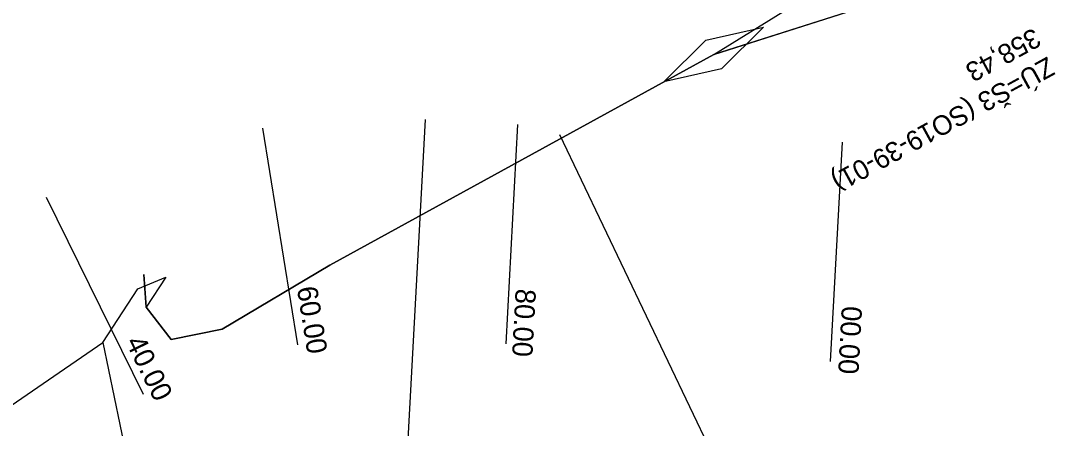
# Model space of a CAD drawing. Extents: x -783978 to -783565, y -1064821 to -1064596.
# Drawn here: x -783930.1 to -783865.7, y -1064776.5 to -1064751.5 of the extents above; entities that cross this region are included whole.
import ezdxf

# ---------------------------------------------------------------- set-up
doc = ezdxf.new("R2010")
doc.units = 0
for name, color, linetype in [('_PS_SO_číslo', 7, 'Continuous'), ('PS 01_02_501', 7, 'Continuous'), ('PS 01_02_502', 7, 'Continuous'), ('SO 01_31_01', 7, 'Continuous'), ('SO 01_50_01', 7, 'Continuous'), ('SO 01_86_02', 7, 'Continuous'), ('SO 01_86_03', 7, 'Continuous')]:
    doc.layers.add(name, color=color, linetype=linetype)

msp = doc.modelspace()

# ---------------------------------------------------------------- linework, layer by layer
at = {"layer": '_PS_SO_číslo'}
for p, q in [((-783896.924, -1064758.44), (-783883.182, -1064787.145)), ((-783925.027, -1064771.233), (-783915.428, -1064817.268))]:
    msp.add_line(p, q, dxfattribs=at)
at = {"layer": 'PS 01_02_501'}
for points in [[(-783952.311, -1064789.972), (-783925.027, -1064771.233), (-783922.857, -1064767.935), (-783921.132, -1064767.225), (-783922.344, -1064769.056), (-783920.816, -1064771.043), (-783917.67, -1064770.417), (-783911.05, -1064766.471), (-783887.429, -1064753.525), (-783871.436, -1064748.425), (-783783.828, -1064700.439), (-783789.362, -1064690.348), (-783735.226, -1064660.707), (-783727.19, -1064659.072), (-783724.297, -1064658.484), (-783715.521, -1064653.988), (-783697.391, -1064644.148), (-783676.268, -1064633.506), (-783655.138, -1064621.894)], [(-783890.501, -1064755.202), (-783887.908, -1064752.647), (-783884.357, -1064751.848), (-783886.95, -1064754.403), (-783890.501, -1064755.202)]]:
    msp.add_lwpolyline(points, dxfattribs=at)
at = {"layer": 'PS 01_02_502'}
for points in [[(-783952.311, -1064789.972), (-783925.027, -1064771.233), (-783922.857, -1064767.935), (-783921.132, -1064767.225), (-783922.344, -1064769.056), (-783920.816, -1064771.043), (-783917.67, -1064770.417), (-783911.05, -1064766.471), (-783887.429, -1064753.525), (-783871.436, -1064748.425), (-783783.828, -1064700.439), (-783789.362, -1064690.348), (-783735.226, -1064660.707), (-783727.19, -1064659.072), (-783724.297, -1064658.484), (-783715.521, -1064653.988), (-783697.391, -1064644.148), (-783676.268, -1064633.506), (-783655.138, -1064621.894)], [(-783890.501, -1064755.202), (-783887.908, -1064752.647), (-783884.357, -1064751.848), (-783886.95, -1064754.403), (-783890.501, -1064755.202)]]:
    msp.add_lwpolyline(points, dxfattribs=at)
at = {"layer": 'SO 01_50_01'}
for p, q in [((-783905.184, -1064757.527), (-783906.791, -1064787.183)), ((-783915.184, -1064758.053), (-783913.042, -1064771.382)), ((-783899.494, -1064757.835), (-783900.225, -1064771.315)), ((-783879.524, -1064758.917), (-783880.254, -1064772.397)), ((-783928.501, -1064762.298), (-783922.534, -1064774.408))]:
    msp.add_line(p, q, dxfattribs=at)
at = {"layer": 'SO 01_86_02'}
msp.add_lwpolyline([(-783922.498, -1064767.051), (-783922.344, -1064769.056), (-783920.816, -1064771.043), (-783917.67, -1064770.417), (-783911.05, -1064766.471), (-783887.429, -1064753.525), (-783877.538, -1064747.393), (-783877.564, -1064745.038)], dxfattribs=at)
at = {"layer": 'SO 01_86_03'}
msp.add_lwpolyline([(-783722.521, -1064661.793), (-783724.821, -1064663.049), (-783735.21, -1064660.697), (-783787.333, -1064689.237), (-783786.817, -1064690.18), (-783783.359, -1064696.803), (-783781.939, -1064699.409), (-783783.828, -1064700.439), (-783871.436, -1064748.425), (-783875.857, -1064749.835), (-783877.538, -1064747.393), (-783875.857, -1064749.835), (-783887.429, -1064753.525), (-783911.05, -1064766.471), (-783917.67, -1064770.417), (-783920.816, -1064771.043), (-783922.344, -1064769.056), (-783922.498, -1064767.051)], dxfattribs=at)

# ---------------------------------------------------------------- texts
at = {"layer": 'SO 01_31_01'}
for s, p in [('358,43', (-783867.738, -1064751.853)), ('ZÚ=Š3 (SO19-39-01)', (-783866.882, -1064753.627))]:
    msp.add_text(s, height=1.2, rotation=208.71105, dxfattribs=at).set_placement(p)
at = {"layer": 'SO 01_50_01'}
for s, rotation, p in [('60.00', 279.12865, (-783913.08, -1064767.876)), ('80.00', 266.89792, (-783899.61, -1064767.906)), ('00.00', 266.89792, (-783879.543, -1064768.972)), ('40.00', 296.23187, (-783923.641, -1064771.204))]:
    msp.add_text(s, height=1.25, rotation=rotation, dxfattribs=at).set_placement(p)

doc.saveas('drawing.dxf')
